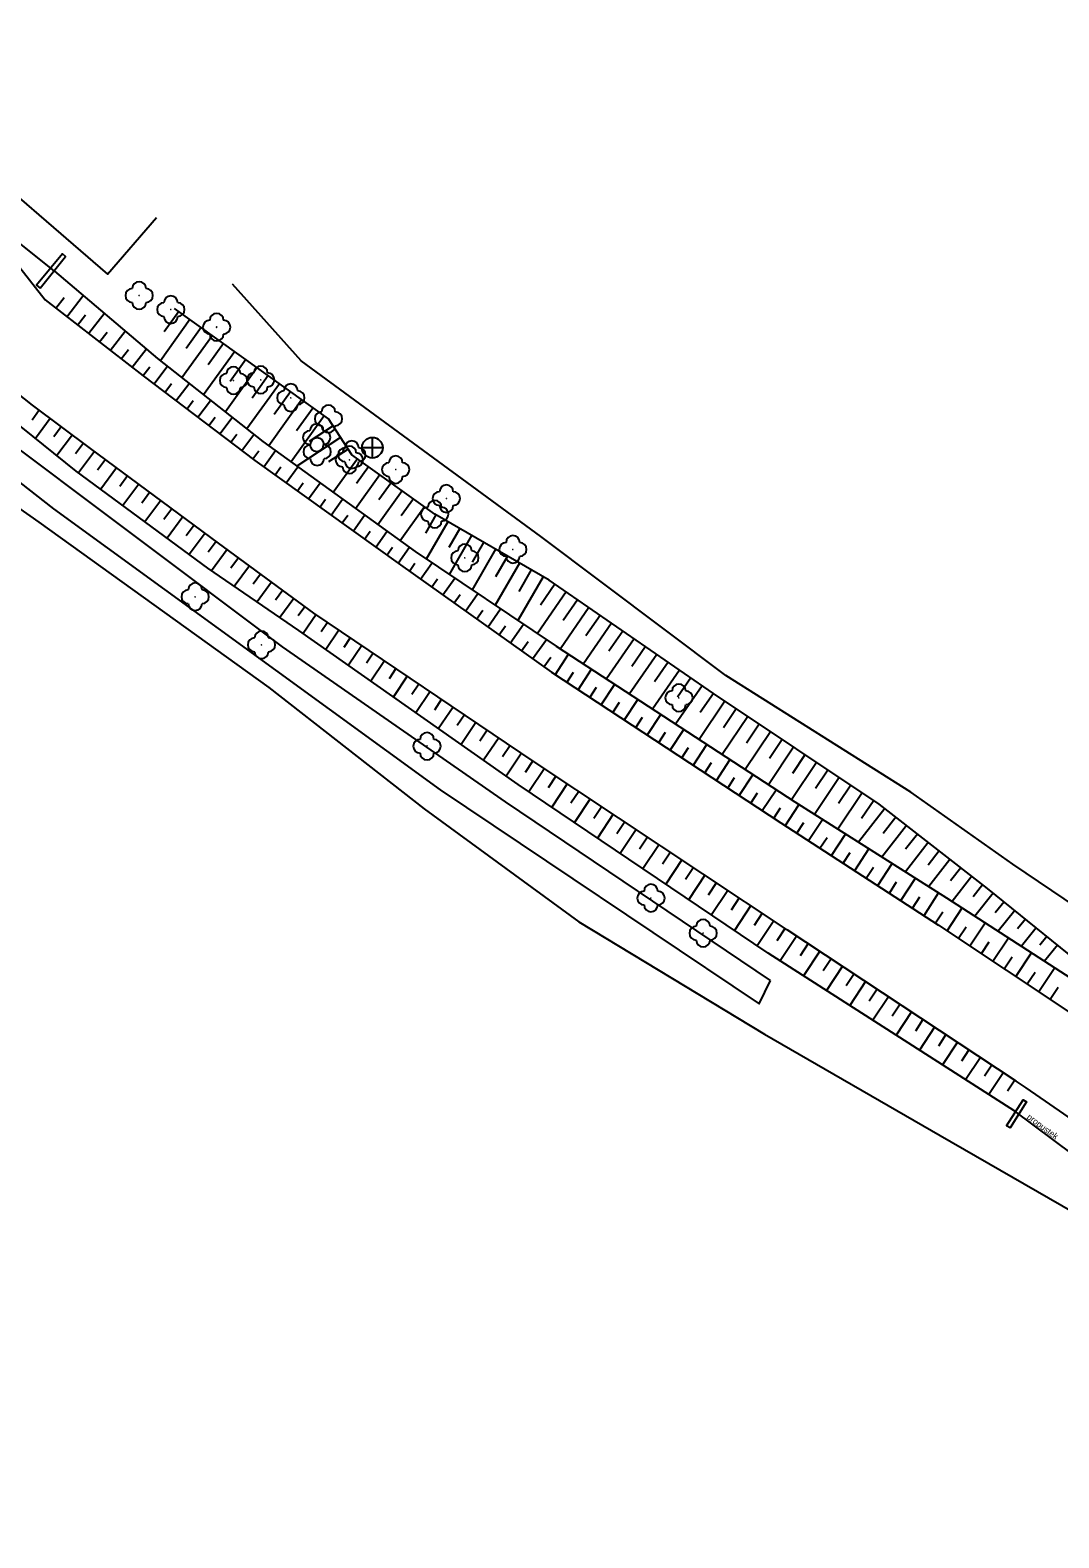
# Model space of a CAD drawing. Extents: x -747135 to -746147, y -1093269 to -1091735.
# Drawn here: x -746888.7 to -746814, y -1092392 to -1092282.5 of the extents above; entities that cross this region are included whole.
import ezdxf

# ---------------------------------------------------------------- set-up
doc = ezdxf.new("R2010")
doc.units = 0
for name, color, linetype in [('101', 7, 'Continuous'), ('1016', 7, 'Continuous'), ('105', 7, 'Continuous'), ('23700', 7, 'Continuous'), ('316', 7, 'Continuous'), ('424', 7, 'Continuous'), ('803', 7, 'Continuous')]:
    doc.layers.add(name, color=color, linetype=linetype)

msp = doc.modelspace()

# ---------------------------------------------------------------- linework, layer by layer
at = {"layer": '101'}
for points in [[(-746817.21, -1092361.03), (-746835.12, -1092349.56), (-746853.28, -1092337.31), (-746869.22, -1092326.11), (-746875.84, -1092321.59), (-746885.39, -1092314.53), (-746906.03, -1092297.92), (-746919.3, -1092287.66), (-746931.74, -1092277.72)], [(-746886.98, -1092300.01), (-746879.5, -1092306.35), (-746871.83, -1092312.38), (-746860.78, -1092320.38), (-746850.53, -1092327.24), (-746833.2, -1092338.57), (-746822.17, -1092345.53), (-746811.56, -1092352.38)], [(-746886.08, -1092303.32), (-746884.89, -1092301.78)], [(-746886.87, -1092302.7), (-746886.26, -1092301.92)], [(-746877.94, -1092302.93), (-746879, -1092304.41)], [(-746810.99, -1092351.49), (-746819.19, -1092344.86), (-746827.07, -1092338.73), (-746839.09, -1092330.7), (-746851.03, -1092322.46), (-746859.35, -1092317.66), (-746865.37, -1092313.34), (-746867.07, -1092310.73), (-746878.25, -1092302.71)], [(-746885.29, -1092303.93), (-746884.71, -1092303.18)], [(-746884.5, -1092304.54), (-746883.36, -1092303.08)], [(-746877.13, -1092303.51), (-746879.28, -1092306.52)], [(-746883.71, -1092305.15), (-746883.15, -1092304.44)], [(-746882.92, -1092305.77), (-746881.84, -1092304.37)], [(-746875.5, -1092304.68), (-746877.71, -1092307.76)], [(-746876.32, -1092304.1), (-746877.41, -1092305.62)], [(-746882.13, -1092306.38), (-746881.6, -1092305.7)], [(-746881.34, -1092306.99), (-746880.31, -1092305.66)], [(-746873.88, -1092305.85), (-746876.14, -1092308.99)], [(-746874.69, -1092305.26), (-746875.81, -1092306.82)], [(-746880.55, -1092307.61), (-746880.05, -1092306.96)], [(-746879.75, -1092308.21), (-746878.78, -1092306.92)], [(-746872.25, -1092307.01), (-746874.56, -1092310.23)], [(-746873.07, -1092306.43), (-746874.21, -1092308.02)], [(-746878.95, -1092308.81), (-746878.47, -1092308.17)], [(-746878.16, -1092309.42), (-746877.2, -1092308.16)], [(-746870.63, -1092308.18), (-746872.99, -1092311.47)], [(-746871.44, -1092307.59), (-746872.61, -1092309.22)], [(-746877.36, -1092310.02), (-746876.89, -1092309.4)], [(-746876.56, -1092310.62), (-746875.63, -1092309.39)], [(-746869, -1092309.34), (-746871.4, -1092312.69)], [(-746869.82, -1092308.76), (-746871.01, -1092310.42)], [(-746888.08, -1092310.11), (-746888.6, -1092310.82)], [(-746875.76, -1092311.22), (-746875.3, -1092310.62)], [(-746874.97, -1092311.83), (-746874.06, -1092310.63)], [(-746867.38, -1092310.51), (-746869.78, -1092313.86)], [(-746868.19, -1092309.93), (-746869.39, -1092311.6)], [(-746887.28, -1092310.71), (-746888.35, -1092312.15)], [(-746886.48, -1092311.31), (-746887.02, -1092312.04)], [(-746866.73, -1092311.25), (-746868.48, -1092312.39)], [(-746885.67, -1092311.9), (-746886.79, -1092313.4)], [(-746884.87, -1092312.5), (-746885.44, -1092313.27)], [(-746874.17, -1092312.43), (-746873.72, -1092311.84)], [(-746873.37, -1092313.03), (-746872.49, -1092311.86)], [(-746866.19, -1092312.09), (-746869.37, -1092314.16)], [(-746884.07, -1092313.1), (-746885.22, -1092314.65)], [(-746883.26, -1092313.69), (-746883.84, -1092314.47)], [(-746872.57, -1092313.64), (-746872.13, -1092313.06)], [(-746871.76, -1092314.22), (-746870.92, -1092313.04)], [(-746865.64, -1092312.93), (-746867.07, -1092313.86)], [(-746864.96, -1092313.64), (-746866.72, -1092316.08)], [(-746882.46, -1092314.29), (-746883.61, -1092315.84)], [(-746881.66, -1092314.88), (-746882.23, -1092315.66)], [(-746870.95, -1092314.81), (-746870.53, -1092314.22)], [(-746870.14, -1092315.39), (-746869.3, -1092314.21)], [(-746863.33, -1092314.8), (-746865.1, -1092317.26)], [(-746864.15, -1092314.22), (-746865.03, -1092315.44)], [(-746880.85, -1092315.47), (-746882, -1092317.03)], [(-746880.05, -1092316.07), (-746880.62, -1092316.85)], [(-746869.32, -1092315.97), (-746868.9, -1092315.39)], [(-746868.51, -1092316.55), (-746867.68, -1092315.39)], [(-746861.71, -1092315.97), (-746863.48, -1092318.43)], [(-746862.52, -1092315.38), (-746863.4, -1092316.61)], [(-746879.24, -1092316.66), (-746880.4, -1092318.22)], [(-746867.7, -1092317.14), (-746867.28, -1092316.56)], [(-746866.88, -1092317.72), (-746866.06, -1092316.56)], [(-746860.08, -1092317.13), (-746861.86, -1092319.6)], [(-746860.9, -1092316.55), (-746861.78, -1092317.78)], [(-746878.44, -1092317.26), (-746879.02, -1092318.04)], [(-746877.64, -1092317.85), (-746878.79, -1092319.41)], [(-746866.07, -1092318.3), (-746865.66, -1092317.72)], [(-746865.26, -1092318.88), (-746864.44, -1092317.73)], [(-746859.27, -1092317.71), (-746860.03, -1092319.04)], [(-746858.4, -1092318.21), (-746859.97, -1092320.92)], [(-746876.83, -1092318.45), (-746877.41, -1092319.23)], [(-746876.03, -1092319.04), (-746877.18, -1092320.6)], [(-746864.45, -1092319.47), (-746864.04, -1092318.89)], [(-746863.63, -1092320.05), (-746862.82, -1092318.91)], [(-746857.53, -1092318.71), (-746858.33, -1092320.09)], [(-746856.67, -1092319.21), (-746858.3, -1092322.04)], [(-746875.22, -1092319.64), (-746875.8, -1092320.42)], [(-746874.42, -1092320.23), (-746875.56, -1092321.78)], [(-746862.82, -1092320.63), (-746862.41, -1092320.06)], [(-746862.01, -1092321.21), (-746861.2, -1092320.08)], [(-746854.94, -1092320.21), (-746856.64, -1092323.15)], [(-746855.8, -1092319.71), (-746856.63, -1092321.15)], [(-746873.61, -1092320.82), (-746874.17, -1092321.58)], [(-746872.81, -1092321.42), (-746873.91, -1092322.91)], [(-746861.19, -1092321.79), (-746860.79, -1092321.22)], [(-746860.38, -1092322.37), (-746859.55, -1092321.21)], [(-746853.2, -1092321.21), (-746854.97, -1092324.27)], [(-746854.07, -1092320.71), (-746854.94, -1092322.21)], [(-746872, -1092322.01), (-746872.54, -1092322.74)], [(-746871.2, -1092322.6), (-746872.25, -1092324.04)], [(-746859.56, -1092322.95), (-746859.14, -1092322.36)], [(-746858.75, -1092323.53), (-746857.88, -1092322.32)], [(-746851.47, -1092322.21), (-746853.3, -1092325.38)], [(-746852.34, -1092321.71), (-746853.24, -1092323.27)], [(-746870.39, -1092323.19), (-746870.91, -1092323.9)], [(-746869.59, -1092323.79), (-746870.6, -1092325.17)], [(-746857.94, -1092324.11), (-746857.49, -1092323.49)], [(-746857.12, -1092324.7), (-746856.22, -1092323.43)], [(-746849.8, -1092323.31), (-746851.89, -1092326.33)], [(-746850.63, -1092322.74), (-746851.67, -1092324.26)], [(-746868.78, -1092324.38), (-746869.28, -1092325.05)], [(-746856.31, -1092325.28), (-746855.85, -1092324.63)], [(-746855.49, -1092325.86), (-746854.56, -1092324.54)], [(-746848.16, -1092324.44), (-746850.22, -1092327.44)], [(-746848.98, -1092323.88), (-746850.02, -1092325.38)], [(-746867.97, -1092324.96), (-746868.9, -1092326.34)], [(-746867.14, -1092325.52), (-746867.61, -1092326.22)], [(-746854.68, -1092326.44), (-746854.2, -1092325.77)], [(-746853.86, -1092327.02), (-746852.9, -1092325.66)], [(-746846.51, -1092325.58), (-746848.55, -1092328.53)], [(-746847.33, -1092325.01), (-746848.36, -1092326.5)], [(-746866.31, -1092326.08), (-746867.26, -1092327.49)], [(-746865.48, -1092326.64), (-746865.96, -1092327.35)], [(-746853.05, -1092327.6), (-746852.56, -1092326.91)], [(-746852.24, -1092328.18), (-746851.23, -1092326.77)], [(-746844.86, -1092326.71), (-746846.88, -1092329.63)], [(-746845.69, -1092326.15), (-746846.7, -1092327.61)], [(-746864.65, -1092327.2), (-746865.62, -1092328.64)], [(-746863.82, -1092327.76), (-746864.31, -1092328.49)], [(-746851.42, -1092328.76), (-746850.91, -1092328.04)], [(-746850.6, -1092329.33), (-746849.62, -1092327.83)], [(-746843.22, -1092327.85), (-746845.2, -1092330.72)], [(-746844.04, -1092327.28), (-746845.04, -1092328.73)], [(-746863, -1092328.32), (-746863.99, -1092329.79)], [(-746862.17, -1092328.88), (-746862.67, -1092329.62)], [(-746849.76, -1092329.88), (-746849.27, -1092329.13)], [(-746848.93, -1092330.42), (-746847.95, -1092328.93)], [(-746841.57, -1092328.99), (-746843.53, -1092331.82)], [(-746842.4, -1092328.42), (-746843.38, -1092329.85)], [(-746861.34, -1092329.44), (-746862.35, -1092330.94)], [(-746860.51, -1092330), (-746861.02, -1092330.75)], [(-746848.09, -1092330.97), (-746847.6, -1092330.22)], [(-746847.25, -1092331.52), (-746846.27, -1092330.02)], [(-746839.93, -1092330.12), (-746841.85, -1092332.91)], [(-746840.75, -1092329.55), (-746841.72, -1092330.96)], [(-746859.68, -1092330.55), (-746860.71, -1092332.09)], [(-746858.85, -1092331.11), (-746859.37, -1092331.89)], [(-746846.42, -1092332.07), (-746845.93, -1092331.32)], [(-746845.58, -1092332.62), (-746844.6, -1092331.12)], [(-746838.27, -1092331.25), (-746840.14, -1092334.04)], [(-746839.1, -1092330.69), (-746840.06, -1092332.08)], [(-746858.02, -1092331.67), (-746859.08, -1092333.24)], [(-746857.19, -1092332.23), (-746857.72, -1092333.02)], [(-746844.75, -1092333.17), (-746844.25, -1092332.42)], [(-746843.91, -1092333.72), (-746842.92, -1092332.21)], [(-746836.61, -1092332.36), (-746838.46, -1092335.13)], [(-746837.44, -1092331.8), (-746838.37, -1092333.19)], [(-746856.36, -1092332.79), (-746857.44, -1092334.39)], [(-746855.53, -1092333.35), (-746856.08, -1092334.16)], [(-746843.07, -1092334.26), (-746842.58, -1092333.51)], [(-746842.24, -1092334.81), (-746841.25, -1092333.31)], [(-746834.95, -1092333.47), (-746836.79, -1092336.22)], [(-746835.78, -1092332.91), (-746836.7, -1092334.3)], [(-746854.7, -1092333.91), (-746855.8, -1092335.54)], [(-746853.87, -1092334.47), (-746854.43, -1092335.29)], [(-746841.4, -1092335.36), (-746840.91, -1092334.61)], [(-746840.57, -1092335.91), (-746839.58, -1092334.4)], [(-746833.28, -1092334.58), (-746835.11, -1092337.32)], [(-746834.11, -1092334.02), (-746835.03, -1092335.4)], [(-746853.05, -1092335.03), (-746854.17, -1092336.69)], [(-746852.22, -1092335.59), (-746852.78, -1092336.42)], [(-746839.73, -1092336.46), (-746839.23, -1092335.7)], [(-746838.89, -1092337.01), (-746837.9, -1092335.5)], [(-746831.62, -1092335.69), (-746833.44, -1092338.41)], [(-746832.45, -1092335.14), (-746833.36, -1092336.5)], [(-746851.38, -1092336.14), (-746852.51, -1092337.83)], [(-746850.55, -1092336.69), (-746851.11, -1092337.54)], [(-746838.06, -1092337.56), (-746837.56, -1092336.8)], [(-746837.22, -1092338.1), (-746836.23, -1092336.59)], [(-746829.96, -1092336.8), (-746831.75, -1092339.49)], [(-746830.79, -1092336.25), (-746831.69, -1092337.6)], [(-746849.72, -1092337.25), (-746850.85, -1092338.95)], [(-746848.88, -1092337.8), (-746849.45, -1092338.65)], [(-746836.39, -1092338.65), (-746835.89, -1092337.9)], [(-746835.55, -1092339.2), (-746834.55, -1092337.68)], [(-746828.29, -1092337.91), (-746830.06, -1092340.55)], [(-746829.13, -1092337.36), (-746830.01, -1092338.69)], [(-746848.05, -1092338.35), (-746849.19, -1092340.07)], [(-746847.22, -1092338.9), (-746847.79, -1092339.77)], [(-746834.71, -1092339.75), (-746834.22, -1092338.99)], [(-746833.88, -1092340.3), (-746832.89, -1092338.77)], [(-746826.65, -1092339.05), (-746828.56, -1092341.5)], [(-746827.46, -1092338.47), (-746828.34, -1092339.78)], [(-746846.38, -1092339.46), (-746847.53, -1092341.19)], [(-746845.55, -1092340.01), (-746846.13, -1092340.88)], [(-746833.04, -1092340.84), (-746832.54, -1092340.07)], [(-746832.2, -1092341.38), (-746831.19, -1092339.84)], [(-746825.86, -1092339.67), (-746826.78, -1092340.85)], [(-746844.72, -1092340.56), (-746845.87, -1092342.31)], [(-746843.88, -1092341.12), (-746844.47, -1092341.99)], [(-746831.36, -1092341.93), (-746830.85, -1092341.15)], [(-746830.52, -1092342.47), (-746829.5, -1092340.9)], [(-746825.07, -1092340.28), (-746826.86, -1092342.57)], [(-746824.28, -1092340.9), (-746825.15, -1092342)], [(-746843.05, -1092341.67), (-746844.22, -1092343.42)], [(-746842.22, -1092342.22), (-746842.8, -1092343.1)], [(-746829.68, -1092343.01), (-746829.17, -1092342.23)], [(-746828.84, -1092343.56), (-746827.81, -1092341.97)], [(-746823.5, -1092341.51), (-746825.16, -1092343.65)], [(-746822.71, -1092342.12), (-746823.51, -1092343.15)], [(-746841.39, -1092342.78), (-746842.56, -1092344.54)], [(-746840.55, -1092343.33), (-746841.14, -1092344.21)], [(-746828, -1092344.1), (-746827.48, -1092343.3)], [(-746827.16, -1092344.65), (-746826.12, -1092343.04)], [(-746821.92, -1092342.74), (-746823.46, -1092344.72)], [(-746821.13, -1092343.35), (-746821.87, -1092344.3)], [(-746839.72, -1092343.88), (-746840.9, -1092345.66)], [(-746838.89, -1092344.43), (-746839.48, -1092345.33)], [(-746826.32, -1092345.19), (-746825.8, -1092344.38)], [(-746825.48, -1092345.73), (-746824.43, -1092344.11)], [(-746820.34, -1092343.97), (-746821.76, -1092345.79)], [(-746819.55, -1092344.58), (-746820.23, -1092345.46)], [(-746838.05, -1092344.99), (-746839.24, -1092346.78)], [(-746837.22, -1092345.54), (-746837.82, -1092346.44)], [(-746824.64, -1092346.28), (-746824.11, -1092345.46)], [(-746823.8, -1092346.82), (-746822.74, -1092345.17)], [(-746818.77, -1092345.2), (-746820.11, -1092346.86)], [(-746836.39, -1092346.09), (-746837.58, -1092347.9)], [(-746835.55, -1092346.65), (-746836.15, -1092347.55)], [(-746822.96, -1092347.36), (-746822.43, -1092346.54)], [(-746822.13, -1092347.92), (-746821.03, -1092346.26)], [(-746817.99, -1092345.83), (-746818.63, -1092346.62)], [(-746817.21, -1092346.46), (-746818.42, -1092347.95)], [(-746834.72, -1092347.2), (-746835.93, -1092349.02)], [(-746833.89, -1092347.75), (-746834.49, -1092348.66)], [(-746821.3, -1092348.47), (-746820.74, -1092347.64)], [(-746820.47, -1092349.02), (-746819.35, -1092347.35)], [(-746816.43, -1092347.09), (-746817, -1092347.79)], [(-746815.66, -1092347.72), (-746816.73, -1092349.04)], [(-746833.05, -1092348.3), (-746834.25, -1092350.12)], [(-746832.22, -1092348.86), (-746832.81, -1092349.76)], [(-746819.63, -1092349.58), (-746819.07, -1092348.74)], [(-746818.8, -1092350.13), (-746817.67, -1092348.43)], [(-746814.88, -1092348.35), (-746815.38, -1092348.97)], [(-746814.1, -1092348.98), (-746815.04, -1092350.13)], [(-746831.38, -1092349.41), (-746832.57, -1092351.2)], [(-746830.55, -1092349.96), (-746831.14, -1092350.85)], [(-746817.97, -1092350.69), (-746817.4, -1092349.83)], [(-746817.14, -1092351.24), (-746815.99, -1092349.52)], [(-746829.72, -1092350.51), (-746830.88, -1092352.27)], [(-746828.88, -1092351.06), (-746829.46, -1092351.94)], [(-746816.3, -1092351.79), (-746815.73, -1092350.93)], [(-746815.47, -1092352.35), (-746814.31, -1092350.6)], [(-746828.05, -1092351.61), (-746829.2, -1092353.35)], [(-746827.21, -1092352.16), (-746827.78, -1092353.03)], [(-746814.64, -1092352.9), (-746814.05, -1092352.02)], [(-746826.38, -1092352.72), (-746827.51, -1092354.43)], [(-746825.54, -1092353.27), (-746826.11, -1092354.12)], [(-746824.71, -1092353.82), (-746825.83, -1092355.51)], [(-746823.88, -1092354.37), (-746824.43, -1092355.21)], [(-746823.04, -1092354.92), (-746824.14, -1092356.59)], [(-746822.21, -1092355.47), (-746822.76, -1092356.3)], [(-746821.37, -1092356.02), (-746822.46, -1092357.67)], [(-746820.54, -1092356.58), (-746821.08, -1092357.39)], [(-746819.71, -1092357.13), (-746820.78, -1092358.75)], [(-746818.87, -1092357.68), (-746819.4, -1092358.48)], [(-746818.04, -1092358.23), (-746819.09, -1092359.83)], [(-746817.2, -1092358.78), (-746817.73, -1092359.57)]]:
    msp.add_lwpolyline(points, dxfattribs=at)
at = {"layer": '1016'}
for points in [[(-746816.38, -1092359.35), (-746817.1, -1092358.85), (-746833.74, -1092347.85), (-746852.12, -1092335.65), (-746868.14, -1092324.85), (-746875.06, -1092319.76), (-746884.36, -1092312.88), (-746888.58, -1092309.74), (-746904.34, -1092297.28), (-746918.62, -1092285.83), (-746930.68, -1092276.08)], [(-746901.53, -1092284.52), (-746896.17, -1092291.24), (-746887.66, -1092302.09)], [(-746888.01, -1092301.24), (-746886.17, -1092298.94), (-746886.4, -1092298.75), (-746888.27, -1092301.02), (-746888.01, -1092301.24)], [(-746887.66, -1092302.09), (-746880.53, -1092307.62), (-746872.41, -1092313.76), (-746861.83, -1092321.34), (-746850.87, -1092329.15), (-746834.21, -1092340.08), (-746822.74, -1092347.51), (-746812.92, -1092354.05)], [(-746774.9, -1092388.01), (-746776.84, -1092386.65), (-746785.57, -1092380.41), (-746796.49, -1092372.78), (-746811.92, -1092362.41), (-746816.38, -1092359.35)], [(-746817.82, -1092362.11), (-746816.6, -1092360.2), (-746816.35, -1092360.36), (-746817.55, -1092362.24), (-746817.82, -1092362.11)]]:
    msp.add_lwpolyline(points, dxfattribs=at)
at = {"layer": '23700'}
for points in [[(-746886.98, -1092300.01), (-746924.32, -1092270.13)], [(-746813.02, -1092364.15), (-746817.21, -1092361.03)]]:
    msp.add_lwpolyline(points, dxfattribs=at)
at = {"layer": '316'}
for p, q in [((-746863.13, -1092312.84), (-746864.63, -1092312.83)), ((-746863.88, -1092313.58), (-746863.88, -1092312.08))]:
    msp.add_line(p, q, dxfattribs=at)
msp.add_circle((-746863.88, -1092312.83), 0.75, dxfattribs=at)
at = {"layer": '424'}
for points in [[(-746834.95, -1092351.54), (-746854.21, -1092338.56), (-746870.4, -1092327.3), (-746891.98, -1092311.12), (-746907.14, -1092298.83), (-746919.89, -1092288.73), (-746931.03, -1092280.56), (-746932.04, -1092282.61), (-746911.44, -1092298.22), (-746887.04, -1092317.26), (-746858.96, -1092337.68), (-746835.77, -1092353.23), (-746834.95, -1092351.54)], [(-746938.71, -1092286.05), (-746933.44, -1092286.22), (-746925.65, -1092289.67), (-746915.11, -1092297.76), (-746902.08, -1092308.43), (-746888.12, -1092318.25), (-746871.41, -1092330.26), (-746860.11, -1092339.08), (-746848.88, -1092347.29), (-746835.4, -1092355.44), (-746822.64, -1092362.8), (-746811.22, -1092369.37), (-746805.16, -1092373.94), (-746803.6, -1092378.83), (-746805.87, -1092387.71)], [(-746666.48, -1092509.53), (-746671.18, -1092501.38), (-746679.28, -1092488.1), (-746683.01, -1092480.66), (-746691.02, -1092465.89), (-746695.91, -1092457.38), (-746697.67, -1092451.5), (-746700.29, -1092444.13), (-746704.56, -1092439.88), (-746720.11, -1092421.5), (-746727.2, -1092412.89), (-746738.25, -1092401.15), (-746749.37, -1092389.72), (-746764.79, -1092376.86), (-746776.64, -1092368.43), (-746787.43, -1092361.47), (-746799.53, -1092355.13), (-746817.34, -1092343.1), (-746824.75, -1092337.86), (-746838.2, -1092329.38), (-746851.64, -1092319.28), (-746869.05, -1092306.53), (-746874.05, -1092300.95)]]:
    msp.add_lwpolyline(points, dxfattribs=at)
for centre in [(-746880.82, -1092301.77), (-746878.52, -1092302.8), (-746875.19, -1092304.07), (-746873.97, -1092307.95), (-746871.99, -1092307.9), (-746869.8, -1092309.2), (-746867.07, -1092310.73), (-746867.92, -1092312.1), (-746867.89, -1092313.12), (-746865.55, -1092313.71), (-746865.37, -1092313.34), (-746862.18, -1092314.42), (-746858.5, -1092316.53), (-746859.35, -1092317.66), (-746853.67, -1092320.22), (-746857.16, -1092320.83), (-746876.75, -1092323.66), (-746871.93, -1092327.15), (-746841.61, -1092331), (-746859.91, -1092334.52), (-746843.64, -1092345.55), (-746839.85, -1092348.1)]:
    msp.add_circle(centre, 0.0005, dxfattribs=at)
for centre, start, end in [((-746880.82, -1092301.27), 0, 180), ((-746881.32, -1092301.77), 90, 270), ((-746880.32, -1092301.77), 270, 90), ((-746878.52, -1092302.3), 0, 180), ((-746880.82, -1092302.27), 180, 360), ((-746879.02, -1092302.8), 90, 270), ((-746878.02, -1092302.8), 270, 90), ((-746878.52, -1092303.3), 180, 360), ((-746875.69, -1092304.07), 90, 270), ((-746875.19, -1092303.57), 0, 180), ((-746874.69, -1092304.07), 270, 90), ((-746875.19, -1092304.57), 180, 360), ((-746873.97, -1092307.45), 0, 180), ((-746871.99, -1092307.4), 0, 180), ((-746874.47, -1092307.95), 90, 270), ((-746873.97, -1092308.45), 180, 360), ((-746873.47, -1092307.95), 270, 90), ((-746872.49, -1092307.9), 90, 270), ((-746871.99, -1092308.4), 180, 360), ((-746871.49, -1092307.9), 270, 90), ((-746869.8, -1092308.7), 0, 180), ((-746870.3, -1092309.2), 90, 270), ((-746869.3, -1092309.2), 270, 90), ((-746869.8, -1092309.7), 180, 360), ((-746867.57, -1092310.73), 90, 270), ((-746867.07, -1092310.23), 0, 180), ((-746866.57, -1092310.73), 270, 90), ((-746868.42, -1092312.1), 90, 270), ((-746867.92, -1092311.6), 0, 180), ((-746867.07, -1092311.23), 180, 360), ((-746867.42, -1092312.1), 270, 90), ((-746868.39, -1092313.12), 90, 270), ((-746867.92, -1092312.6), 180, 360), ((-746867.89, -1092312.62), 0, 180), ((-746867.39, -1092313.12), 270, 90), ((-746865.87, -1092313.34), 90, 270), ((-746865.55, -1092313.21), 0, 180), ((-746865.37, -1092312.84), 0, 180), ((-746864.87, -1092313.34), 270, 90), ((-746867.89, -1092313.62), 180, 360), ((-746866.05, -1092313.71), 90, 270), ((-746865.37, -1092313.84), 180, 360), ((-746865.05, -1092313.71), 270, 90), ((-746862.68, -1092314.42), 90, 270), ((-746862.18, -1092313.92), 0, 180), ((-746861.68, -1092314.42), 270, 90), ((-746865.55, -1092314.21), 180, 360), ((-746862.18, -1092314.92), 180, 360), ((-746859, -1092316.53), 90, 270), ((-746858.5, -1092316.03), 0, 180), ((-746858, -1092316.53), 270, 90), ((-746859.85, -1092317.66), 90, 270), ((-746859.35, -1092317.16), 0, 180), ((-746858.5, -1092317.03), 180, 360), ((-746858.85, -1092317.66), 270, 90), ((-746859.35, -1092318.16), 180, 360), ((-746853.67, -1092319.72), 0, 180), ((-746857.66, -1092320.83), 90, 270), ((-746857.16, -1092320.33), 0, 180), ((-746856.66, -1092320.83), 270, 90), ((-746854.17, -1092320.22), 90, 270), ((-746853.17, -1092320.22), 270, 90), ((-746857.16, -1092321.33), 180, 360), ((-746853.67, -1092320.72), 180, 360), ((-746876.75, -1092323.16), 0, 180), ((-746877.25, -1092323.66), 90, 270), ((-746876.25, -1092323.66), 270, 90), ((-746876.75, -1092324.16), 180, 360), ((-746872.43, -1092327.15), 90, 270), ((-746871.93, -1092326.65), 0, 180), ((-746871.43, -1092327.15), 270, 90), ((-746871.93, -1092327.65), 180, 360), ((-746841.61, -1092330.5), 0, 180), ((-746842.11, -1092331), 90, 270), ((-746841.11, -1092331), 270, 90), ((-746841.61, -1092331.5), 180, 360), ((-746859.91, -1092334.02), 0, 180), ((-746860.41, -1092334.52), 90, 270), ((-746859.41, -1092334.52), 270, 90), ((-746859.91, -1092335.02), 180, 360), ((-746843.64, -1092345.05), 0, 180), ((-746844.14, -1092345.55), 90, 270), ((-746843.14, -1092345.55), 270, 90), ((-746843.64, -1092346.05), 180, 360), ((-746840.35, -1092348.1), 90, 270), ((-746839.85, -1092347.6), 0, 180), ((-746839.35, -1092348.1), 270, 90), ((-746839.85, -1092348.6), 180, 360)]:
    msp.add_arc(centre, 0.5, start, end, dxfattribs=at)
at = {"layer": '803'}
msp.add_lwpolyline([(-746894.03, -1092290.82), (-746883.13, -1092300.23), (-746879.57, -1092296.11)], dxfattribs=at)

# ---------------------------------------------------------------- texts
at = {"layer": '105'}
msp.add_text('propustek', height=0.45, rotation=323.5652, dxfattribs=at).set_placement((-746816.38, -1092361.55))

doc.saveas('drawing.dxf')
